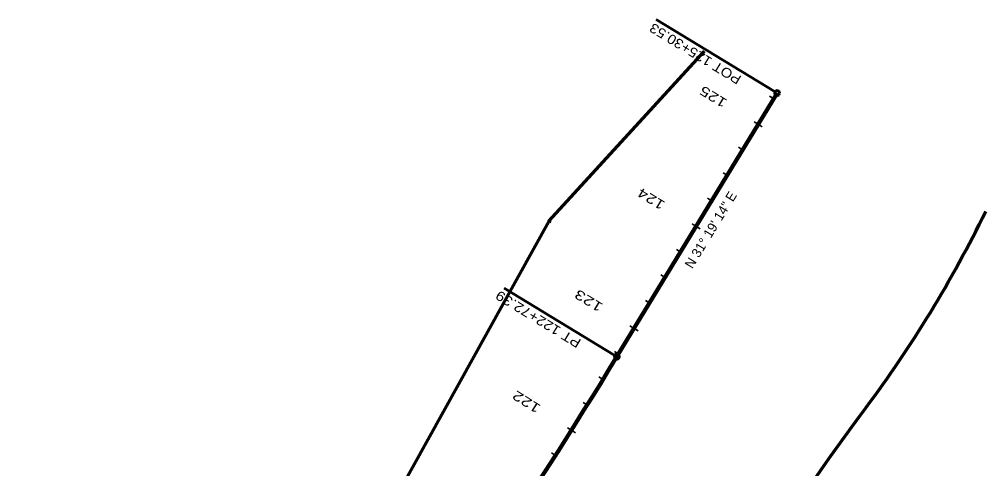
# Model space of a CAD drawing. Extents: x 2717836 to 2719883, y 337327 to 339813.
# Drawn here: x 2719074 to 2719883, y 338626 to 339002 of the extents above; entities that cross this region are included whole.
import ezdxf
from ezdxf.enums import TextEntityAlignment as Align

# ---------------------------------------------------------------- set-up
doc = ezdxf.new("R2010")
doc.units = 0
doc.header["$LTSCALE"] = 3.2
for name, color, linetype, lineweight in [('1', 7, 'Continuous', 106), ('23', 7, 'Continuous', 70), ('31', 7, 'Continuous', 35)]:
    doc.layers.add(name, color=color, linetype=linetype, lineweight=lineweight)

msp = doc.modelspace()

# ---------------------------------------------------------------- hatches: boundary and pattern name
at = {"layer": '23'}
msp.add_hatch(color=256, dxfattribs=at).paths.add_polyline_path([(2719519.189, 338832.652), (2719518.439, 338831.352), (2719517.14, 338832.102), (2719517.89, 338833.402)])

# ---------------------------------------------------------------- linework, layer by layer
at = {"layer": '1'}
msp.add_line((2719574.471, 338719.468), (2719708.661, 338939.994), dxfattribs=at)
msp.add_arc((2715303.107, 341318.594), 5000, 318.95467, 328.67947, dxfattribs=at)
at = {"layer": '23'}
for q in [(2719647.932, 338975), (2719374.169, 338574.501)]:
    msp.add_line((2719517.515, 338832.752), q, dxfattribs=at)
at = {"layer": '23', "lineweight": 25}
msp.add_lwpolyline([(2719519.189, 338832.652), (2719518.439, 338831.352), (2719517.14, 338832.102), (2719517.89, 338833.402)], close=True, dxfattribs=at)
at = {"layer": '23'}
for centre, radius, start, end in [((2718952.338, 339297.151), 1036.78, 323.24732, 333.88925), ((2721482.92, 337405.985), 2122.39, 143.21906, 151.90671)]:
    msp.add_arc(centre, radius, start, end, dxfattribs=at)
at = {"layer": '31', "lineweight": 60}
for p, q in [((2719706.952, 338941.034), (2719607.346, 339001.644)), ((2719572.762, 338720.508), (2719480.205, 338776.828))]:
    msp.add_line(p, q, dxfattribs=at)
at = {"layer": '31'}
for p, q in [((2719705.786, 338935.269), (2719702.369, 338937.348)), ((2719692.79, 338913.912), (2719689.373, 338915.992)), ((2719692.79, 338913.912), (2719696.207, 338911.833)), ((2719679.795, 338892.556), (2719676.378, 338894.635)), ((2719666.799, 338871.199), (2719663.382, 338873.278)), ((2719653.803, 338849.842), (2719650.386, 338851.921)), ((2719640.808, 338828.485), (2719637.391, 338830.564)), ((2719640.808, 338828.485), (2719644.225, 338826.406)), ((2719627.812, 338807.128), (2719624.395, 338809.208)), ((2719614.817, 338785.771), (2719611.399, 338787.851)), ((2719601.821, 338764.415), (2719598.404, 338766.494)), ((2719588.825, 338743.058), (2719585.408, 338745.137)), ((2719588.825, 338743.058), (2719592.242, 338740.978)), ((2719575.83, 338721.701), (2719572.413, 338723.78)), ((2719562.791, 338700.37), (2719559.383, 338702.465)), ((2719549.647, 338679.105), (2719546.25, 338681.216)), ((2719536.396, 338657.905), (2719533.01, 338660.034)), ((2719536.396, 338657.905), (2719539.783, 338655.777)), ((2719523.04, 338636.772), (2719519.664, 338638.917))]:
    msp.add_line(p, q, dxfattribs=at)
at = {"layer": '31', "lineweight": 60}
for centre in [(2719708.661, 338939.994), (2719574.471, 338719.468)]:
    msp.add_circle(centre, 2, dxfattribs=at)

# ---------------------------------------------------------------- texts
at = {"layer": '31'}
for s, rotation, width, p in [('POT 125+30.53', 148.679, 1.15, (2719679.505, 338953.638)), ('125', 148.679, 1.35, (2719667.533, 338933.964)), ('124', 148.679, 1.35, (2719615.55, 338848.537)), ('PT 122+72.39', 148.679, 1.2, (2719545.315, 338733.112)), ('123', 148.679, 1.4, (2719563.568, 338763.109)), ('122', 147.85, 1.4, (2719511.432, 338678.32))]:
    msp.add_text(s, height=8, rotation=rotation, dxfattribs=dict(at, width=width)).set_placement(p)
msp.add_text('N 31° 19\' 14" E', height=8, rotation=58.679, dxfattribs=at).set_placement((2719656.5, 338823.493), align=Align.CENTER)

doc.saveas('drawing.dxf')
